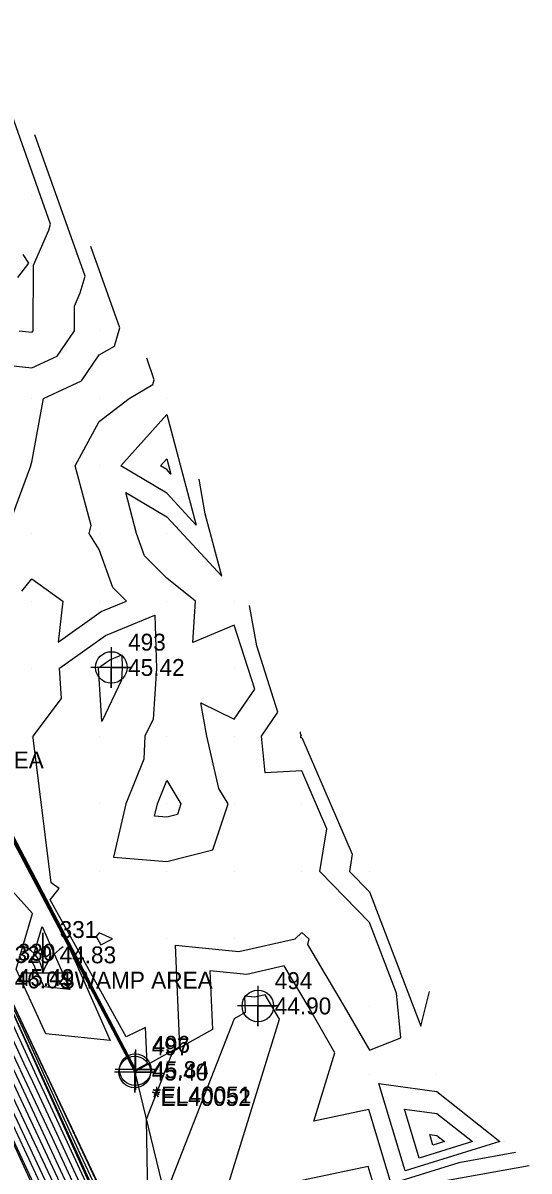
# Model space of a CAD drawing. Extents: x 2090860 to 2091277, y 159470 to 160080.
# Drawn here: x 2091008.7 to 2091083.6, y 159905.6 to 160075.6 of the extents above; entities that cross this region are included whole.
import ezdxf

# ---------------------------------------------------------------- set-up
doc = ezdxf.new("R2010")
doc.units = 0
for name, color, linetype in [('DTM Contours Major', 7, 'Continuous'), ('DTM Contours Minor', 7, 'Continuous'), ('Exist DTM Breakline', 7, 'Continuous'), ('Exist DTM Breakline Cogo Comment', 7, 'Continuous'), ('Exist DTM Breakline Cogo Elevation', 7, 'Continuous'), ('Exist DTM Breakline Cogo Number', 7, 'Continuous'), ('Exist DTM Breakline Cogo Point CELL', 7, 'Continuous'), ('Exist DTM Breakline Underwater', 7, 'Continuous'), ('Exist DTM QL2 LIDAR Elevation Point', 7, 'Continuous'), ('Exist DTM Regular Point CELL', 7, 'Continuous'), ('Exist DTM Regular Point Cogo Elevation', 7, 'Continuous'), ('Exist DTM Regular Point Cogo Number', 7, 'Continuous'), ('Exist Hydro Swamp or Marsh', 7, 'Continuous'), ('Exist Hydro Swamp or Marsh Cogo Comment', 7, 'Continuous'), ('Exist Hydro Swamp or Marsh Cogo Elevation', 7, 'Continuous'), ('Exist Hydro Swamp or Marsh Cogo Number', 7, 'Continuous')]:
    doc.layers.add(name, color=color, linetype=linetype)

msp = doc.modelspace()

# ---------------------------------------------------------------- linework, layer by layer
at = {"layer": 'DTM Contours Major'}
for points in [[(2091021.02, 159898.88), (2091011.64, 159919.46), (2091005.48, 159932.96), (2091005.01, 159933.95), (2090993.09, 159961.19), (2090992.99, 159961.43), (2090991.42, 159965.02), (2090992.97, 159961.45), (2090985.93, 159965.48), (2090984.33, 159968.87), (2090979.62, 159978.84), (2090976.35, 159997.97), (2090975.97, 159998.78), (2090963.78, 160025.21), (2090963.07, 160026.71), (2090951.2, 160052.43), (2090950.87, 160053.13), (2090947.08, 160061.34), (2090947.11, 160061.36)], [(2091021.18, 159890.91), (2091013.64, 159907.17), (2091008.52, 159918.11), (2091005.72, 159924.07), (2091001.85, 159932.41), (2090996.75, 159943.48), (2090989.56, 159959.77), (2090985.43, 159962.14), (2090982.71, 159967.91), (2090974.67, 159984.9), (2090972.74, 159996.2), (2090967.23, 160007.83), (2090960.06, 160023.38), (2090954.32, 160035.48), (2090947.37, 160050.56), (2090945.47, 160054.56), (2090943.25, 160059.37), (2090943.41, 160059.46)], [(2091015.95, 159893.79), (2091005.23, 159916.67), (2090999.39, 159929.13), (2090998.6, 159930.83), (2090988.2, 159953.4), (2090986.13, 159958.11), (2090984.93, 159958.8), (2090981.09, 159966.95), (2090969.73, 159990.96), (2090969.14, 159994.43), (2090958.5, 160016.88), (2090956.34, 160021.56), (2090945.58, 160044.26), (2090943.53, 160048.69), (2090940.07, 160055.99), (2090939.42, 160057.39), (2090939.71, 160057.56)], [(2091008.56, 159991.44), (2091010, 159993.31), (2091014.62, 159990), (2091013.94, 159983.94), (2091020.28, 159988.45), (2091024.04, 159990), (2091022.03, 159992.03), (2091020, 159997.65), (2091018.5, 160000), (2091018.81, 160001.19), (2091016.45, 160010), (2091020, 160016.57), (2091024.42, 160020), (2091027.96, 160022.04), (2091028.16, 160022.76), (2091027.03, 160025.94)], [(2091030, 160005.95), (2091023.2, 160010), (2091030, 160017.63), (2091034.38, 160001.23), (2091030, 160005.95)], [(2091028.61, 159960), (2091030, 159963.46), (2091032.1, 159960), (2091031.57, 159958.43), (2091030, 159958.04), (2091028.18, 159958.18), (2091028.61, 159960)], [(2091011.55, 159941.86), (2091015.66, 159932.53), (2091011.83, 159932.93), (2091010.04, 159936.78), (2091011.55, 159941.86)], [(2091061.17, 159901.88), (2091059.83, 159906.32), (2091038.54, 159901.84), (2091046.68, 159928.13), (2091045.57, 159930.07), (2091044.58, 159931.73), (2091043.03, 159931.38), (2091041.51, 159931.53), (2091041.61, 159929.1), (2091039.97, 159928.18), (2091029.72, 159901.93)], [(2091069.42, 159909.46), (2091068.94, 159911.06), (2091070, 159910.92), (2091071.15, 159910), (2091069.42, 159909.46)], [(2091083.65, 159906.42), (2091065.23, 159903.13)]]:
    msp.add_lwpolyline(points, dxfattribs=at)
at = {"layer": 'DTM Contours Minor'}
for points in [[(2091008.16, 160030), (2091010, 160029.8), (2091010.14, 160029.86), (2091010.23, 160030), (2091010.27, 160039.73), (2091012.56, 160044.89), (2091012.81, 160045.78), (2091002.22, 160075.55)], [(2090959.85, 160067.93), (2090961.6, 160063.4), (2090960.85, 160060.54), (2090969.39, 160041.13), (2090973.54, 160038.91), (2090972.08, 160035.98), (2090978.49, 160021.2), (2090985.46, 160019.57), (2090990, 160012.68), (2090994.86, 160015.14), (2090995.92, 160020), (2090999.04, 160020.96), (2091000, 160022.24), (2091004.96, 160025.04), (2091010, 160024.5), (2091013.77, 160026.23), (2091016.33, 160030), (2091016.34, 160033.66), (2091017.2, 160035.6), (2091017.93, 160038.1), (2091010.49, 160059.02)], [(2091024.64, 159892.33), (2091016.88, 159908.81), (2091011.98, 159919.53), (2091008.77, 159926.57), (2091005.22, 159934.11), (2090999.13, 159948.03), (2090993.22, 159961.58), (2090990.48, 159967.83), (2090989.15, 159970.88), (2090979.66, 159991.83), (2090976.79, 159998.21), (2090966.5, 160020.93), (2090964.43, 160025.54), (2090952.99, 160050.77), (2090952.06, 160052.86), (2090948.15, 160061.46), (2090948, 160061.81), (2090948.15, 160061.88)], [(2091025.1, 159892.47), (2091012.73, 159918.74), (2091012.33, 159919.61), (2091012.07, 159920.19), (2091005.42, 159934.27), (2091005.16, 159934.86), (2090993.44, 159961.73), (2090992.08, 159964.84), (2090989.38, 159971.02), (2090984.01, 159982.89), (2090977.04, 159998.36), (2090971.59, 160010.41), (2090964.7, 160025.71), (2090959.13, 160038), (2090952.36, 160053.05), (2090950.66, 160056.79), (2090948.36, 160061.92), (2090950.64, 160063.03)], [(2091021.99, 159891.26), (2091013.06, 159910.52), (2091009.34, 159918.47), (2091007.31, 159922.8), (2091002.67, 159932.8), (2090998.89, 159941), (2090990.42, 159960.19), (2090985.55, 159962.98), (2090983.11, 159968.15), (2090975.91, 159983.38), (2090973.65, 159996.65), (2090969.41, 160005.57), (2090960.99, 160023.84), (2090956.51, 160033.29), (2090948.33, 160051.03), (2090946.82, 160054.2), (2090944.21, 160059.86), (2090944.34, 160059.93)], [(2091022.8, 159891.62), (2091012.48, 159913.86), (2091010.16, 159918.83), (2091008.89, 159921.53), (2091003.48, 159933.2), (2091001.03, 159938.51), (2090991.28, 159960.6), (2090985.68, 159963.81), (2090983.52, 159968.39), (2090977.15, 159981.87), (2090974.55, 159997.09), (2090971.6, 160003.31), (2090961.92, 160024.3), (2090958.7, 160031.1), (2090949.28, 160051.5), (2090948.17, 160053.84), (2090945.17, 160060.35), (2090945.26, 160060.41)], [(2091023.61, 159891.97), (2091011.91, 159917.21), (2091010.98, 159919.19), (2091010.47, 159920.27), (2091004.29, 159933.59), (2091003.17, 159936.03), (2090992.14, 159961.02), (2090985.8, 159964.65), (2090983.92, 159968.63), (2090978.38, 159980.35), (2090975.45, 159997.53), (2090973.78, 160001.04), (2090962.85, 160024.75), (2090960.88, 160028.91), (2090950.24, 160051.97), (2090949.52, 160053.48), (2090946.13, 160060.85), (2090946.19, 160060.88)], [(2091014.79, 159900.48), (2091006.87, 159917.39), (2091002.56, 159926.6), (2091000.23, 159931.62), (2090992.48, 159948.44), (2090987.84, 159958.94), (2090985.18, 159960.47), (2090981.9, 159967.43), (2090972.2, 159987.93), (2090970.94, 159995.32), (2090962.86, 160012.36), (2090958.2, 160022.47), (2090949.95, 160039.87), (2090945.45, 160049.62), (2090942.77, 160055.27), (2090941.34, 160058.38), (2090941.56, 160058.51)], [(2091014.22, 159903.83), (2091007.7, 159917.75), (2091004.14, 159925.33), (2091001.04, 159932.01), (2090994.62, 159945.96), (2090988.7, 159959.36), (2090985.3, 159961.31), (2090982.3, 159967.67), (2090973.44, 159986.41), (2090971.84, 159995.76), (2090965.05, 160010.1), (2090959.13, 160022.93), (2090952.14, 160037.68), (2090946.41, 160050.09), (2090944.12, 160054.92), (2090942.3, 160058.87), (2090942.49, 160058.99)], [(2091016.53, 159890.45), (2091004.41, 159916.31), (2090997.81, 159930.39), (2090997.79, 159930.43), (2090986.07, 159955.89), (2090985.27, 159957.7), (2090984.81, 159957.96), (2090980.68, 159966.71), (2090968.5, 159992.47), (2090968.24, 159993.99), (2090956.31, 160019.15), (2090955.41, 160021.1), (2090943.39, 160046.45), (2090942.57, 160048.22), (2090938.72, 160056.35), (2090938.47, 160056.9), (2090938.79, 160057.09)], [(2091015.37, 159897.14), (2091006.05, 159917.03), (2091000.98, 159927.86), (2090999.42, 159931.22), (2090990.34, 159950.92), (2090986.99, 159958.53), (2090985.05, 159959.63), (2090981.49, 159967.19), (2090970.97, 159989.44), (2090970.04, 159994.87), (2090960.68, 160014.62), (2090957.27, 160022.02), (2090947.76, 160042.06), (2090944.49, 160049.15), (2090941.42, 160055.63), (2090940.38, 160057.88), (2090940.64, 160058.04)], [(2091007.2, 160002.8), (2091009.86, 160010), (2091009.89, 160010.11), (2091010, 160010.55), (2091011.74, 160020), (2091017.4, 160022.6), (2091020, 160026.43), (2091022.26, 160027.74), (2091023.05, 160030.43), (2091018.76, 160042.48)], [(2091008.69, 160041.31), (2091009.54, 160040), (2091007.88, 160037.88)], [(2091030, 160009.45), (2091029.07, 160010), (2091030, 160011.04), (2091030.6, 160008.8), (2091030, 160009.45)], [(2091003.92, 159961.56), (2091011.8, 159946.48), (2091023.47, 159924.14), (2091025.34, 159920.58), (2091027.08, 159921.55), (2091026.86, 159926.9), (2091024.01, 159925.5), (2091012.72, 159945.77), (2091014.08, 159947.45), (2091012.91, 159948.28), (2091010.22, 159969.78), (2091010.2, 159970), (2091014.4, 159975.6), (2091014.14, 159980.06), (2091020.93, 159984.89), (2091028.24, 159987.9), (2091028.46, 159980.03), (2091027.97, 159972.51), (2091026.77, 159970), (2091026.62, 159966.62), (2091023.96, 159960), (2091022.1, 159952.1), (2091030, 159951.48), (2091036.82, 159953.18), (2091039.1, 159960), (2091037.73, 159962.27), (2091035.92, 159970), (2091035.04, 159974.96), (2091040, 159972.54), (2091043.02, 159976.98), (2091040, 159986.45), (2091033.86, 159983.86), (2091034.26, 159990), (2091030, 159993.39), (2091026.71, 159996.71), (2091025.52, 160000), (2091023.93, 160006.07), (2091030, 160002.45), (2091038.17, 159993.67), (2091035.69, 160002.92), (2091034.79, 160008.03)], [(2091003.52, 159962), (2091011.65, 159946.45), (2091018.18, 159933.96), (2091025.29, 159920.37), (2091031.93, 159924.06), (2091031.3, 159939.05), (2091040.66, 159938.12), (2091049, 159940), (2091050, 159940.93), (2091051.04, 159940), (2091050.82, 159939.18), (2091056.29, 159930.02), (2091060, 159923.53), (2091064.66, 159925.34), (2091064.02, 159931.97), (2091060, 159942.41), (2091052.66, 159950), (2091053.69, 159956.31), (2091050, 159964.85), (2091044.57, 159964.57), (2091044.04, 159970), (2091046.45, 159973.55), (2091043.33, 159983.35), (2091042.26, 159989.34)], [(2091020.38, 159972.19), (2091019.91, 159980.14), (2091021.57, 159981.32), (2091023.36, 159982.06), (2091023.42, 159980.13), (2091023.3, 159978.29), (2091020.38, 159972.19)], [(2090997.61, 159972.98), (2091009.77, 159949.72), (2091011.5, 159946.42), (2091012.88, 159943.77), (2091015.66, 159938.47), (2091021.61, 159924.96), (2091012.11, 159925.97), (2091007.68, 159935.5), (2091010.13, 159943.75), (2090994.37, 159961.26)], [(2091049.74, 159970.65), (2091049.78, 159970.45), (2091049.88, 159970.12), (2091049.8, 159970), (2091049.82, 159969.82), (2091050, 159969.83), (2091057.47, 159952.53), (2091057.05, 159950), (2091060, 159946.96), (2091067.64, 159927.09), (2091068.89, 159932.22)], [(2091021.99, 159940), (2091020, 159940.88), (2091019.57, 159940.34), (2091020.24, 159939.14), (2091021.99, 159940)], [(2091081.66, 159908.37), (2091073.27, 159906.87), (2091063.23, 159903.77), (2091059.94, 159914.75), (2091051.77, 159913.04), (2091054.89, 159923.12), (2091050.93, 159930.04), (2091047.38, 159936), (2091041.85, 159934.75), (2091036.4, 159935.29), (2091036.77, 159926.58), (2091030.87, 159923.3), (2091026.97, 159913.29), (2091027.29, 159893.6)], [(2091065.29, 159905.67), (2091061.42, 159918.58), (2091070, 159917.42), (2091079.34, 159910), (2091065.29, 159905.67)], [(2091067.36, 159907.57), (2091065.18, 159914.82), (2091070, 159914.17), (2091075.25, 159910), (2091067.36, 159907.57)]]:
    msp.add_lwpolyline(points, dxfattribs=at)
at = {"layer": 'Exist DTM Breakline'}
for points in [[(2090956.62, 160065.42), (2090978.09, 160018.86), (2090997.9, 159973.05), (2091025.36, 159920.65)], [(2090955.18, 160064.83), (2090976.65, 160018.47), (2090997.43, 159972.93), (2091025.27, 159920.29)], [(2091060.14, 159819.74), (2091040.42, 159857.57), (2091023.86, 159892.08), (2091004.98, 159933.93), (2090988.92, 159970.75), (2090947.97, 160061.8)], [(2091061.63, 159820.63), (2091041.56, 159858.32), (2091025.18, 159892.5), (2091005.43, 159934.28), (2090989.69, 159971.2), (2090948.62, 160062.01)], [(2091054.85, 159814.3), (2091016.78, 159888.98), (2090997.77, 159930.43), (2090980.35, 159966.51), (2090937.84, 160056.58)]]:
    msp.add_lwpolyline(points, dxfattribs=at)
at = {"layer": 'Exist DTM Breakline Cogo Point CELL'}
for points in [[(2091025.27, 159923.29), (2091025.27, 159917.29), (2091025.27, 159920.29), (2091028.27, 159920.29), (2091022.27, 159920.29)], [(2091025.36, 159923.65), (2091025.36, 159917.65), (2091025.36, 159920.65), (2091028.36, 159920.65), (2091022.36, 159920.65)]]:
    msp.add_lwpolyline(points, dxfattribs=at)
for centre in [(2091025.27, 159920.29), (2091025.36, 159920.65)]:
    msp.add_circle(centre, 2.34, dxfattribs=at)
at = {"layer": 'Exist DTM Breakline Underwater'}
msp.add_lwpolyline([(2091025.27, 159920.29), (2091031.24, 159895.66), (2091047.08, 159861.35)], dxfattribs=at)
at = {"layer": 'Exist DTM QL2 LIDAR Elevation Point'}
for p, q in [((2091010, 160050), (2091010, 160050)), ((2091010, 160040), (2091010, 160040)), ((2091010, 160030), (2091010, 160030)), ((2091020, 160030), (2091020, 160030)), ((2091010, 160020), (2091010, 160020)), ((2091020, 160020), (2091020, 160020)), ((2091030, 160020), (2091030, 160020)), ((2091010, 160010), (2091010, 160010)), ((2091020, 160010), (2091020, 160010)), ((2091030, 160010), (2091030, 160010)), ((2091010, 160000), (2091010, 160000)), ((2091020, 160000), (2091020, 160000)), ((2091030, 160000), (2091030, 160000)), ((2091010, 159990), (2091010, 159990)), ((2091020, 159990), (2091020, 159990)), ((2091030, 159990), (2091030, 159990)), ((2091040, 159990), (2091040, 159990)), ((2091010, 159980), (2091010, 159980)), ((2091030, 159980), (2091030, 159980)), ((2091040, 159980), (2091040, 159980)), ((2091010, 159970), (2091010, 159970)), ((2091020, 159970), (2091020, 159970)), ((2091030, 159970), (2091030, 159970)), ((2091040, 159970), (2091040, 159970)), ((2091050, 159970), (2091050, 159970)), ((2091020, 159960), (2091020, 159960)), ((2091030, 159960), (2091030, 159960)), ((2091040, 159960), (2091040, 159960)), ((2091050, 159960), (2091050, 159960)), ((2091020, 159950), (2091020, 159950)), ((2091030, 159950), (2091030, 159950)), ((2091040, 159950), (2091040, 159950)), ((2091050, 159950), (2091050, 159950)), ((2091060, 159950), (2091060, 159950)), ((2091020, 159940), (2091020, 159940)), ((2091030, 159940), (2091030, 159940)), ((2091040, 159940), (2091040, 159940)), ((2091050, 159940), (2091050, 159940)), ((2091060, 159940), (2091060, 159940)), ((2091060, 159930), (2091060, 159930)), ((2091060, 159920), (2091060, 159920)), ((2091070, 159920), (2091070, 159920)), ((2091070, 159910), (2091070, 159910)), ((2091080, 159910), (2091080, 159910))]:
    msp.add_line(p, q, dxfattribs=at)
at = {"layer": 'Exist DTM Regular Point CELL'}
for points in [[(2091021.78, 159983.17), (2091021.78, 159977.17), (2091021.78, 159980.17), (2091024.78, 159980.17), (2091018.78, 159980.17)], [(2091043.49, 159933.08), (2091043.49, 159927.08), (2091043.49, 159930.08), (2091046.49, 159930.08), (2091040.49, 159930.08)]]:
    msp.add_lwpolyline(points, dxfattribs=at)
for centre in [(2091021.78, 159980.17), (2091043.49, 159930.08)]:
    msp.add_circle(centre, 2.34, dxfattribs=at)
at = {"layer": 'Exist Hydro Swamp or Marsh'}
msp.add_line((2091011.64, 159937.64), (2091011.64, 159937.64), dxfattribs=at)
msp.add_lwpolyline([(2091008.42, 159934.97), (2091011.64, 159934.97), (2091011.64, 159940.89), (2091011.64, 159934.97), (2091014.87, 159934.97)], dxfattribs=at)
for centre, radius, start, end in [((2091007.04, 159934.64), 4.61, 4.1403, 67.535), ((2091018.48, 159932.7), 7.21, 122.1274, 161.6222)]:
    msp.add_arc(centre, radius, start, end, dxfattribs=at)

# ---------------------------------------------------------------- texts
at = {"layer": 'Exist DTM Breakline Cogo Comment'}
for s, p in [('*EL40052', (2091027.77, 159915.29)), ('*EL40051', (2091027.86, 159915.65))]:
    msp.add_text(s, height=2.5, dxfattribs=at).set_placement(p)
at = {"layer": 'Exist DTM Breakline Cogo Elevation'}
for s, p in [('46.04', (2091007.48, 159932.68)), ('45.49', (2091007.93, 159933.03)), ('45.40', (2091027.77, 159919.04)), ('45.84', (2091027.86, 159919.4))]:
    msp.add_text(s, height=2.5, dxfattribs=at).set_placement(p)
at = {"layer": 'Exist DTM Breakline Cogo Number'}
for s, p in [('330', (2091007.93, 159936.78)), ('329', (2091007.48, 159936.43)), ('496', (2091027.86, 159923.15)), ('497', (2091027.77, 159922.79))]:
    msp.add_text(s, height=2.5, dxfattribs=at).set_placement(p)
at = {"layer": 'Exist DTM Regular Point Cogo Elevation'}
for s, p in [('45.42', (2091024.28, 159978.92)), ('44.90', (2091045.99, 159928.83))]:
    msp.add_text(s, height=2.5, dxfattribs=at).set_placement(p)
at = {"layer": 'Exist DTM Regular Point Cogo Number'}
for s, p in [('493', (2091024.28, 159982.67)), ('494', (2091045.99, 159932.58))]:
    msp.add_text(s, height=2.5, dxfattribs=at).set_placement(p)
at = {"layer": 'Exist Hydro Swamp or Marsh Cogo Comment'}
for p in [(2090989.13, 159965.23), (2091014.14, 159932.64)]:
    msp.add_text('SWAMP AREA', height=2.5, dxfattribs=at).set_placement(p)
at = {"layer": 'Exist Hydro Swamp or Marsh Cogo Elevation'}
msp.add_text('44.83', height=2.5, dxfattribs=at).set_placement((2091014.14, 159936.39))
at = {"layer": 'Exist Hydro Swamp or Marsh Cogo Number'}
msp.add_text('331', height=2.5, dxfattribs=at).set_placement((2091014.14, 159940.14))

doc.saveas('drawing.dxf')
